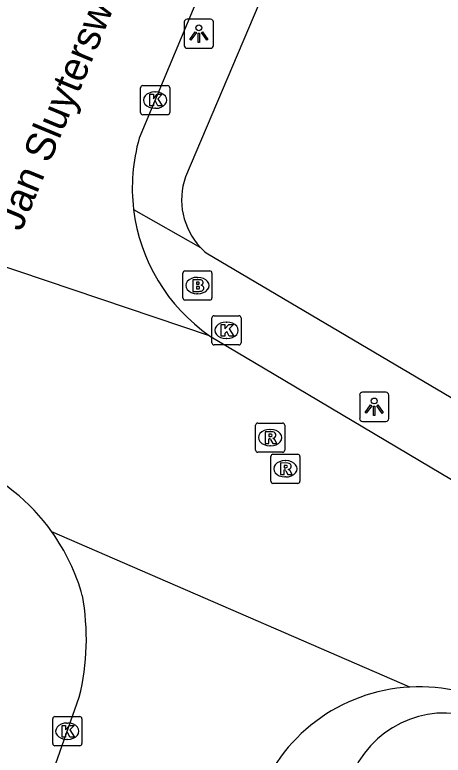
# Model space of a CAD drawing. Extents: x 163268 to 164360, y 381529 to 382285.
# Drawn here: x 163908.02 to 163922.72, y 381955.99 to 381981.39 of the extents above; entities that cross this region are included whole.
import ezdxf

# ---------------------------------------------------------------- set-up
doc = ezdxf.new("R2010")
doc.units = 0
for name, color, linetype in [('IMGEO_Brandkraan', 7, 'Continuous'), ('IMGEO_Kolk', 7, 'Continuous'), ('IMGEO_Lichtpunt', 7, 'Continuous'), ('IMGEO_Openbare_ruimte_label', 7, 'Continuous'), ('IMGEO_Rijbaan_lokaal_open', 7, 'Continuous'), ('IMGEO_Rioolput', 7, 'Continuous'), ('IMGEO_Voetpad_open', 7, 'Continuous')]:
    doc.layers.add(name, color=color, linetype=linetype)

msp = doc.modelspace()

# ---------------------------------------------------------------- linework, layer by layer
at = {"layer": 'IMGEO_Brandkraan'}
for p, q in [((163913.787, 381971.677), (163913.787, 381972.529)), ((163913.862, 381972.603), (163914.714, 381972.603)), ((163914.275, 381972.383), (163914.3, 381972.383)), ((163914.788, 381972.529), (163914.788, 381971.677)), ((163914.298, 381971.823), (163914.273, 381971.823)), ((163914.714, 381971.603), (163913.862, 381971.603))]:
    msp.add_line(p, q, dxfattribs=at)
for points in [[(163913.787, 381971.677), (163913.787, 381972.529)], [(163913.862, 381972.603), (163914.714, 381972.603)], [(163914.788, 381972.529), (163914.788, 381971.677)], [(163914.135, 381972.303), (163914.135, 381971.903), (163914.348, 381971.903)], [(163914.366, 381972.303), (163914.135, 381972.303)], [(163914.314, 381972.222), (163914.26, 381972.222), (163914.26, 381972.146)], [(163914.26, 381972.146), (163914.313, 381972.146)], [(163914.322, 381972.07), (163914.26, 381972.07), (163914.26, 381971.989)], [(163914.26, 381971.989), (163914.322, 381971.989)], [(163914.714, 381971.603), (163913.862, 381971.603)]]:
    msp.add_lwpolyline(points, dxfattribs=at)
for centre, radius, start, end in [((163913.864, 381972.527), 0.0765, 91.552, 178.448), ((163913.864, 381972.527), 0.0765, 91.552, 178.448), ((163914.712, 381972.527), 0.0765, 1.552, 88.448), ((163914.712, 381972.527), 0.0765, 1.552, 88.448), ((163914.315, 381972.184), 0.0379, 267.8285, 90.9355), ((163914.37, 381972.158), 0.145, 59.4692, 91.5367), ((163914.395, 381972.205), 0.0922, 285.5137, 58.1501), ((163914.323, 381972.029), 0.0404, 269.8759, 90.5077), ((163914.354, 381972.154), 0.251, 268.6676, 293.5347), ((163914.4, 381972.013), 0.105, 301.3115, 78.989), ((163913.864, 381971.679), 0.0765, 181.552, 268.448), ((163913.864, 381971.679), 0.0765, 181.552, 268.448), ((163914.712, 381971.679), 0.0765, 271.552, 358.448), ((163914.712, 381971.679), 0.0765, 271.552, 358.448)]:
    msp.add_arc(centre, radius, start, end, dxfattribs=at)
for centre, major_axis, ratio, start_param, end_param in [((163914.274, 381972.103), (-0.387, 0.002), 0.722429, 4.712389, 7.853982), ((163914.299, 381972.103), (-0.39, 0.002), 0.717154, 1.570796, 4.712389)]:
    msp.add_ellipse(centre, major_axis=major_axis, ratio=ratio, start_param=start_param, end_param=end_param, dxfattribs=at)
at = {"layer": 'IMGEO_Kolk'}
for p, q in [((163912.338, 381978.036), (163912.338, 381978.888)), ((163912.413, 381978.962), (163913.265, 381978.962)), ((163912.826, 381978.742), (163912.851, 381978.742)), ((163913.339, 381978.888), (163913.339, 381978.036)), ((163913.265, 381977.962), (163912.413, 381977.962)), ((163912.849, 381978.182), (163912.824, 381978.182)), ((163914.788, 381970.14), (163914.788, 381970.992)), ((163914.863, 381971.066), (163915.715, 381971.066)), ((163915.789, 381970.992), (163915.789, 381970.14)), ((163915.276, 381970.846), (163915.301, 381970.846)), ((163915.299, 381970.286), (163915.274, 381970.286)), ((163915.715, 381970.066), (163914.863, 381970.066)), ((163909.322, 381956.392), (163909.322, 381957.244)), ((163909.397, 381957.318), (163910.249, 381957.318)), ((163910.323, 381957.244), (163910.323, 381956.392)), ((163909.81, 381957.098), (163909.835, 381957.098)), ((163909.833, 381956.538), (163909.808, 381956.538)), ((163910.249, 381956.318), (163909.397, 381956.318))]:
    msp.add_line(p, q, dxfattribs=at)
for points in [[(163912.338, 381978.036), (163912.338, 381978.888)], [(163912.413, 381978.962), (163913.265, 381978.962)], [(163913.339, 381978.888), (163913.339, 381978.036)], [(163912.659, 381978.662), (163912.782, 381978.662), (163912.782, 381978.511), (163912.912, 381978.662), (163913.076, 381978.662), (163912.93, 381978.511), (163913.083, 381978.262), (163912.931, 381978.262), (163912.846, 381978.426), (163912.782, 381978.359), (163912.782, 381978.262), (163912.659, 381978.262), (163912.659, 381978.662)], [(163913.265, 381977.962), (163912.413, 381977.962)], [(163914.788, 381970.14), (163914.788, 381970.992)], [(163914.863, 381971.066), (163915.715, 381971.066)], [(163915.789, 381970.992), (163915.789, 381970.14)], [(163915.109, 381970.766), (163915.232, 381970.766), (163915.232, 381970.615), (163915.362, 381970.766), (163915.526, 381970.766), (163915.38, 381970.615), (163915.533, 381970.366), (163915.381, 381970.366), (163915.296, 381970.53), (163915.232, 381970.463), (163915.232, 381970.366), (163915.109, 381970.366), (163915.109, 381970.766)], [(163915.715, 381970.066), (163914.863, 381970.066)], [(163909.322, 381956.392), (163909.322, 381957.244)], [(163909.397, 381957.318), (163910.249, 381957.318)], [(163910.323, 381957.244), (163910.323, 381956.392)], [(163909.643, 381957.018), (163909.766, 381957.018), (163909.766, 381956.867), (163909.896, 381957.018), (163910.06, 381957.018), (163909.914, 381956.867), (163910.067, 381956.618), (163909.915, 381956.618), (163909.83, 381956.782), (163909.766, 381956.715), (163909.766, 381956.618), (163909.643, 381956.618), (163909.643, 381957.018)], [(163910.249, 381956.318), (163909.397, 381956.318)]]:
    msp.add_lwpolyline(points, dxfattribs=at)
for centre, start, end in [((163912.415, 381978.886), 91.552, 178.448), ((163912.415, 381978.886), 91.552, 178.448), ((163913.263, 381978.886), 1.552, 88.448), ((163913.263, 381978.886), 1.552, 88.448), ((163912.415, 381978.038), 181.552, 268.448), ((163912.415, 381978.038), 181.552, 268.448), ((163913.263, 381978.038), 271.552, 358.448), ((163913.263, 381978.038), 271.552, 358.448), ((163914.865, 381970.99), 91.552, 178.448), ((163914.865, 381970.99), 91.552, 178.448), ((163915.713, 381970.99), 1.552, 88.448), ((163915.713, 381970.99), 1.552, 88.448), ((163914.865, 381970.142), 181.552, 268.448), ((163914.865, 381970.142), 181.552, 268.448), ((163915.713, 381970.142), 271.552, 358.448), ((163915.713, 381970.142), 271.552, 358.448), ((163909.399, 381957.242), 91.552, 178.448), ((163909.399, 381957.242), 91.552, 178.448), ((163910.247, 381957.242), 1.552, 88.448), ((163910.247, 381957.242), 1.552, 88.448), ((163909.399, 381956.394), 181.552, 268.448), ((163909.399, 381956.394), 181.552, 268.448), ((163910.247, 381956.394), 271.552, 358.448), ((163910.247, 381956.394), 271.552, 358.448)]:
    msp.add_arc(centre, 0.0765, start, end, dxfattribs=at)
for centre, major_axis, ratio, start_param, end_param in [((163912.825, 381978.462), (-0.387, 0.002), 0.722429, 4.712389, 7.853982), ((163912.85, 381978.462), (-0.39, 0.002), 0.717154, 1.570796, 4.712389), ((163915.275, 381970.566), (-0.387, 0.002), 0.722429, 4.712389, 7.853982), ((163915.3, 381970.566), (-0.39, 0.002), 0.717154, 1.570796, 4.712389), ((163909.809, 381956.818), (-0.387, 0.002), 0.722429, 4.712389, 7.853982), ((163909.834, 381956.818), (-0.39, 0.002), 0.717154, 1.570796, 4.712389)]:
    msp.add_ellipse(centre, major_axis=major_axis, ratio=ratio, start_param=start_param, end_param=end_param, dxfattribs=at)
at = {"layer": 'IMGEO_Lichtpunt'}
for p, q in [((163913.839, 381981.142), (163913.839, 381980.335)), ((163913.839, 381981.142), (163913.839, 381980.335)), ((163914.741, 381981.237), (163913.933, 381981.237)), ((163914.741, 381981.237), (163913.933, 381981.237)), ((163914.835, 381980.335), (163914.835, 381981.142)), ((163914.835, 381980.335), (163914.835, 381981.142)), ((163913.933, 381980.241), (163914.741, 381980.241)), ((163913.933, 381980.241), (163914.741, 381980.241)), ((163919.857, 381968.346), (163919.857, 381967.539)), ((163919.857, 381968.346), (163919.857, 381967.539)), ((163920.759, 381968.441), (163919.951, 381968.441)), ((163920.759, 381968.441), (163919.951, 381968.441)), ((163920.853, 381967.539), (163920.853, 381968.346)), ((163920.853, 381967.539), (163920.853, 381968.346)), ((163919.951, 381967.445), (163920.759, 381967.445)), ((163919.951, 381967.445), (163920.759, 381967.445))]:
    msp.add_line(p, q, dxfattribs=at)
for points in [[(163914.213, 381980.806), (163914.252, 381980.778), (163914.064, 381980.516), (163914.026, 381980.543), (163914.213, 381980.806)], [(163914.315, 381980.758), (163914.362, 381980.758), (163914.362, 381980.436), (163914.315, 381980.436), (163914.315, 381980.758)], [(163914.425, 381980.778), (163914.463, 381980.805), (163914.65, 381980.543), (163914.611, 381980.515), (163914.425, 381980.778)], [(163920.231, 381968.01), (163920.27, 381967.982), (163920.082, 381967.72), (163920.044, 381967.747), (163920.231, 381968.01)], [(163920.333, 381967.962), (163920.38, 381967.962), (163920.38, 381967.64), (163920.333, 381967.64), (163920.333, 381967.962)], [(163920.443, 381967.982), (163920.481, 381968.009), (163920.668, 381967.747), (163920.629, 381967.719), (163920.443, 381967.982)]]:
    msp.add_lwpolyline(points, dxfattribs=at)
for centre in [(163914.338, 381980.94), (163920.356, 381968.144)]:
    msp.add_circle(centre, 0.0994, dxfattribs=at)
for centre, start, end in [((163913.933, 381981.142), 90, 180), ((163913.933, 381981.142), 90, 180), ((163914.741, 381981.142), 0, 90), ((163914.741, 381981.142), 0, 90), ((163913.933, 381980.335), 180, 270), ((163913.933, 381980.335), 180, 270), ((163914.741, 381980.335), 270, 0), ((163914.741, 381980.335), 270, 360), ((163919.951, 381968.346), 90, 180), ((163919.951, 381968.346), 90, 180), ((163920.759, 381968.346), 0, 90), ((163920.759, 381968.346), 0, 90), ((163919.951, 381967.539), 180, 270), ((163919.951, 381967.539), 180, 270), ((163920.759, 381967.539), 270, 0), ((163920.759, 381967.539), 270, 360)]:
    msp.add_arc(centre, 0.0946, start, end, dxfattribs=at)
at = {"layer": 'IMGEO_Rijbaan_lokaal_open'}
for points in [[(163921.296, 381998.657), (163912.293, 381977.155)], [(163914.704, 381970.381), (163896.886, 381976.383)], [(163914.704, 381970.381), (163916.926, 381969.068), (163927.633, 381962.707)], [(163921.582, 381958.333), (163909.295, 381963.652)], [(163884.733, 381885.565), (163910.234, 381957.988)]]:
    msp.add_lwpolyline(points, dxfattribs=at)
for centre, radius, start, end in [((163918.228, 381975.452), 6.175, 163.9875, 186.8889), ((163918.23, 381975.453), 6.177, 186.8948, 235.1883), ((163903.593, 381959.579), 7.007, 35.5378, 66.9112), ((163903.613, 381959.598), 6.98, 15.5292, 35.5053), ((163902.273, 381959.967), 8.204, 346.0401, 10.5353), ((163921.896, 381952.453), 5.888, 93.0591, 161.0531), ((163921.895, 381952.444), 5.897, 59.5129, 93.0437)]:
    msp.add_arc(centre, radius, start, end, dxfattribs=at)
at = {"layer": 'IMGEO_Rioolput'}
for p, q in [((163916.282, 381966.461), (163916.282, 381967.313)), ((163916.357, 381967.387), (163917.209, 381967.387)), ((163917.283, 381967.313), (163917.283, 381966.461)), ((163916.77, 381967.167), (163916.795, 381967.167)), ((163916.793, 381966.607), (163916.768, 381966.607)), ((163917.209, 381966.387), (163916.357, 381966.387)), ((163916.882, 381966.317), (163917.734, 381966.317)), ((163916.807, 381965.391), (163916.807, 381966.243)), ((163917.295, 381966.097), (163917.32, 381966.097)), ((163917.808, 381966.243), (163917.808, 381965.391)), ((163917.318, 381965.537), (163917.293, 381965.537)), ((163917.734, 381965.317), (163916.882, 381965.317))]:
    msp.add_line(p, q, dxfattribs=at)
for points in [[(163916.282, 381966.461), (163916.282, 381967.313)], [(163916.357, 381967.387), (163917.209, 381967.387)], [(163917.283, 381967.313), (163917.283, 381966.461)], [(163916.871, 381967.085), (163916.619, 381967.087), (163916.619, 381966.687)], [(163916.619, 381966.687), (163916.743, 381966.687), (163916.743, 381966.849), (163916.754, 381966.849)], [(163916.797, 381967.006), (163916.743, 381967.006), (163916.743, 381966.925)], [(163916.743, 381966.925), (163916.795, 381966.925)], [(163916.801, 381966.82), (163916.872, 381966.687), (163917.012, 381966.687), (163916.947, 381966.813)], [(163917.209, 381966.387), (163916.357, 381966.387)], [(163916.882, 381966.317), (163917.734, 381966.317)], [(163916.807, 381965.391), (163916.807, 381966.243)], [(163917.808, 381966.243), (163917.808, 381965.391)], [(163917.396, 381966.015), (163917.144, 381966.017), (163917.144, 381965.617)], [(163917.144, 381965.617), (163917.268, 381965.617), (163917.268, 381965.779), (163917.279, 381965.779)], [(163917.322, 381965.936), (163917.268, 381965.936), (163917.268, 381965.855)], [(163917.268, 381965.855), (163917.32, 381965.855)], [(163917.326, 381965.75), (163917.397, 381965.617), (163917.537, 381965.617), (163917.472, 381965.743)], [(163917.734, 381965.317), (163916.882, 381965.317)]]:
    msp.add_lwpolyline(points, dxfattribs=at)
for centre, radius, start, end in [((163916.359, 381967.311), 0.0765, 91.552, 178.448), ((163916.359, 381967.311), 0.0765, 91.552, 178.448), ((163917.207, 381967.311), 0.0765, 1.552, 88.448), ((163917.207, 381967.311), 0.0765, 1.552, 88.448), ((163916.87, 381966.975), 0.109, 350.3612, 89.416), ((163916.753, 381966.796), 0.0533, 26.0293, 88.6989), ((163916.779, 381967.114), 0.19, 274.7715, 282.9687), ((163916.803, 381966.91), 0.0964, 77.0061, 93.1865), ((163916.817, 381966.967), 0.0378, 276.6634, 79.6772), ((163916.868, 381966.975), 0.112, 277.5842, 350.9817), ((163916.852, 381966.76), 0.108, 29.5134, 73.7905), ((163916.359, 381966.463), 0.0765, 181.552, 268.448), ((163916.359, 381966.463), 0.0765, 181.552, 268.448), ((163916.884, 381966.241), 0.0765, 91.552, 178.448), ((163916.884, 381966.241), 0.0765, 91.552, 178.448), ((163917.207, 381966.463), 0.0765, 271.552, 358.448), ((163917.207, 381966.463), 0.0765, 271.552, 358.448), ((163917.732, 381966.241), 0.0765, 1.552, 88.448), ((163917.732, 381966.241), 0.0765, 1.552, 88.448), ((163917.278, 381965.726), 0.0533, 26.0293, 88.6989), ((163917.304, 381966.044), 0.19, 274.7715, 282.9687), ((163917.328, 381965.84), 0.0964, 77.0061, 93.1865), ((163917.342, 381965.897), 0.0378, 276.6634, 79.6772), ((163917.395, 381965.905), 0.109, 350.3612, 89.416), ((163917.393, 381965.905), 0.112, 277.5842, 350.9817), ((163917.377, 381965.69), 0.108, 29.5134, 73.7905), ((163916.884, 381965.393), 0.0765, 181.552, 268.448), ((163916.884, 381965.393), 0.0765, 181.552, 268.448), ((163917.732, 381965.393), 0.0765, 271.552, 358.448), ((163917.732, 381965.393), 0.0765, 271.552, 358.448)]:
    msp.add_arc(centre, radius, start, end, dxfattribs=at)
for centre, major_axis, ratio, start_param, end_param in [((163916.769, 381966.887), (-0.387, 0.002), 0.722429, 4.712389, 7.853982), ((163916.794, 381966.887), (-0.39, 0.002), 0.717154, 1.570796, 4.712389), ((163917.294, 381965.817), (-0.387, 0.002), 0.722429, 4.712389, 7.853982), ((163917.319, 381965.817), (-0.39, 0.002), 0.717154, 1.570796, 4.712389)]:
    msp.add_ellipse(centre, major_axis=major_axis, ratio=ratio, start_param=start_param, end_param=end_param, dxfattribs=at)
at = {"layer": 'IMGEO_Voetpad_open'}
for points in [[(163923.233, 381997.859), (163913.877, 381975.828)], [(163912.098, 381974.711), (163914.394, 381973.409)], [(163914.587, 381973.225), (163941.767, 381957.19), (163964.779, 381943.352)]]:
    msp.add_lwpolyline(points, dxfattribs=at)
for centre, radius, start, end in [((163916.138, 381975.046), 2.392, 160.9282, 223.1999), ((163916.063, 381974.967), 2.283, 223.0196, 229.7155), ((163922.783, 381953.981), 3.46, 66.9213, 154.2498)]:
    msp.add_arc(centre, radius, start, end, dxfattribs=at)

# ---------------------------------------------------------------- texts
at = {"layer": 'IMGEO_Openbare_ruimte_label'}
msp.add_text('Jan Sluytersweg', height=1, rotation=67.4859, dxfattribs=at).set_placement((163908.24, 381973.927))

doc.saveas('drawing.dxf')
